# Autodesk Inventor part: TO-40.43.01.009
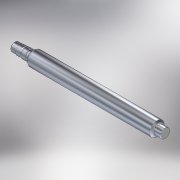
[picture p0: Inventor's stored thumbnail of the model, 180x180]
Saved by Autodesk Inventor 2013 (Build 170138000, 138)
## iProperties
Shininess: 86.0
Length Units: 11269
Angle Units: 11279
Time Units: 11290
Mass Units: 11283
Length Display Precision: 3
Angle Display Precision: 2
Created: 2001-11
Part Number: TO-40.43.01.009
Material: Steel, Mild
Document SubType Name: Modeling
Designer: SOleg
Density: 7.86 g/cm^3
Density: 0.0
Volumn: 0.0
Area: 0.0
PropertySet Name: Model Information
Control State: 0
Master: False
Checked Out: False
Checked Out Date: 2008-10-09
Last Check In Date: 2008-10-09
Author: SOleg
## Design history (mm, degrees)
sketch "Sketch3"
  geometry: L1 (512.5, 27.5)-(512.5, -27.5) reference; L2 (512.5, 34.226)-(512.5, -34.226) reference; C1 r 4 at (598.5, 0)
  constraints: 1 centre point
  dimensions: "d70" = 8 diameter of C1; "d76" = 86 distance from line of L2 C1.centre
extrude "ExtrusionMidplane2" cut sketch "Sketch3" stored distance "d71" = 60; taper "d72" = 0 deg
revolve "RevolutionAngle1" stored, may be unused: angle "d56" = 360 deg
node "WorkAxis1"
body "Solid1"
node "WorkPlane2"
node "WorkPlane1"
chamfer "Chamfer1" distance "d57" = 10; stored, may be unused: angle "d58" = 28 deg, second distance "d74" = 10
chamfer "Chamfer2" distance "d59" = 10; stored, may be unused: angle "d60" = 30 deg, second distance "d75" = 10
sketch "Sketch1"
  geometry: L1 (-614.5, 22)-(-614.5, 0); L2 (-612.5, 24)-(-614.5, 22); L3 (-586.5, 24)-(-612.5, 24); L4 (-584.5, 26)-(-586.5, 24); L5 (-561, 26)-(-584.5, 26); L6 (-559.5, 24.5)-(-561, 26); L7 (-554.5, 24.5)-(-559.5, 24.5); L8 (-554.5, 26.5)-(-554.5, 24.5); L9 (-553.5, 27.5)-(-554.5, 26.5); L10 (-534.1, 27.5)-(-553.5, 27.5); L11 (-534.1, 23.8)-(-534.1, 27.5); L12 (-528.5, 23.8)-(-534.1, 23.8); L13 (-528.5, 27.5)-(-528.5, 23.8); L14 (-512.5, 27.5)-(-528.5, 27.5); L15 (-512.5, 40)-(-512.5, 27.5); L16 (179.5, 40)-(-512.5, 40); L17 (179.5, 24)-(179.5, 40); L18 (184.5, 24)-(179.5, 24); L19 (186.5, 26)-(184.5, 24); L20 (217.5, 26)-(186.5, 26); L21 (219.5, 24)-(217.5, 26); L22 (219.5, 0)-(219.5, 24); L23 (-614.5, 0)-(219.5, 0); L24 (-614.5, 0)-(219.5, 0)
  constraints: 48 end point, 8 horizontal, 5 vertical
  dimensions: "d1" = 2 horizontal distance of L21.start L20.start; "d3" = 2 horizontal distance of L21.start L20.start; "d5" = 2 horizontal distance of L19.start L18.start; "d7" = 2 horizontal distance of L19.start L18.start; "d9" = 40 horizontal distance of L22.start L16.start; "d11" = 5 distance of L18.start L17.start; "d13" = 40 distance of L17.start L21.start; "d15" = 26 vertical distance of L19.start L22.start; "d17" = 834 distance of L1.end L22.start; "d19" = 16 distance of L14.start L13.start; "d21" = 27.5 vertical distance of L13.start L1.end; "d23" = 23.8 vertical distance of L12.start L1.end; "d25" = 27.5 vertical distance of L10.start L1.end; "d27" = 5.6 distance of L12.start L11.start; "d29" = 2 horizontal distance of L2.start L1.start; "d31" = 2 horizontal distance of L2.start L1.start; "d33" = 1 horizontal distance of L9.start L8.start; "d35" = 1 horizontal distance of L9.start L8.start; "d37" = 24.5 vertical distance of L7.start L1.end; "d39" = 26 vertical distance of L4.start L1.end; "d41" = 5 distance of L7.start L6.start; "d43" = 135 deg angle of L7 L6; "d45" = 2 horizontal distance of L4.start L3.start; "d47" = 2 horizontal distance of L4.start L3.start; "d49" = 28 horizontal distance of L1.start L3.start; "d51" = 60 horizontal distance of L1.start L7.start; "d53" = 26 vertical distance of L5.start L1.end; "d55" = 102 horizontal distance of L1.end L15.start
other parameters: "d0" = 2 (derived), "d2" = 2 (derived), "d4" = 2 (derived), "d6" = 2 (derived), "d10" = 5 (derived), "d14" = 26 (derived), "d16" = 629 (derived), "d18" = 16 (derived), "d20" = 27.5 (derived), "d22" = 23.8 (derived), "d24" = 27.5 (derived), "d26" = 5.6 (derived), "d28" = 2 (derived), "d30" = 2 (derived), "d32" = 1 (derived), "d34" = 1 (derived), "d36" = 24.5 (derived), "d38" = 26 (derived), "d40" = 5 (derived), "d42" = 135 deg (derived), "d44" = 2 (derived), "d46" = 2 (derived), "d48" = 28 (derived), "d52" = 26 (derived), "d54" = 102 (derived), "d61" = 65 (derived), "d69" = 8 (derived)
